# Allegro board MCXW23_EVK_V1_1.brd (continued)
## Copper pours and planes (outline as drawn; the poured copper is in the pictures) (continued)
GND on TOP (solid shape): 52.91,75.6 53,75.64 53.09,75.6 53.2,75.53 53.32,75.5 53.68,75.5 53.78,75.52 53.87,75.57 53.95,75.59 54.02,75.56 54.05,75.53 54.09,75.51 54.15,75.37 54.04,75.28 53.91,75.21 53.86,75.07 53.86,73.97 53.92,73.82 54.07,73.76 54.97,73.76 55.02,73.76 55.06,73.77 55.29,73.75 55.41,73.55 55.41,73.45 55.29,73.25 55.06,73.23 55.02,73.24 54.97,73.24 54.07,73.24 53.92,73.18 53.86,73.03 53.86,72.82 53.14,72.82 53.14,74.05 53.08,74.19 52.94,74.26 52.85,74.3 52.82,74.39 52.82,75.34 52.83,75.36 52.84,75.41 52.84,75.46 52.84,75.54 52.89,75.58
GND on TOP (solid shape): 76.41,99.86 76.41,94.62 76.33,94.5 76.2,94.53 75.99,94.74 75.88,94.81 75.75,94.84 75.46,94.84 75.42,94.89 75.34,94.97 75.34,95.06 75.34,95.12 75.32,95.17 75.32,95.24 75.35,95.3 75.4,95.37 75.42,95.45 75.42,96.05 75.41,96.12 75.37,96.18 75.41,96.24 75.42,96.3 75.42,96.7 75.4,96.76 75.37,96.82 75.41,96.88 75.42,96.95 75.42,97.55 75.41,97.61 75.38,97.67 75.35,97.76 75.39,97.84 75.52,98.03 75.57,98.25 75.4,98.65 75,98.82 74.88,98.81 74.76,98.77 74.58,98.75 74.44,98.86 74.4,98.91 74.36,99 74.4,99.09 74.47,99.2 74.5,99.32 74.5,99.68 74.49,99.75 74.47,99.81 74.49,100.05 74.7,100.16 76.11,100.16
GND on TOP (solid shape): 61.65,77.44 61.87,77.44 61.93,77.34 61.89,77.23 61.84,77.16 61.82,77.07 61.82,75.97 61.88,75.82 62.03,75.76 63.16,75.76 63.16,75.24 62.03,75.24 61.88,75.18 61.82,75.03 61.82,73.89 61.77,73.68 61.57,73.59 60,73.59 59.87,73.56 59.76,73.49 58.75,72.48 57.59,73.64 57.59,76.04 57.87,76.04 58.02,76.1 58.08,76.25 58.08,77.15 58.08,77.2 58.07,77.24 58.05,77.26 58.05,77.42 58.24,77.42 58.25,77.41 59.05,77.41 59.2,77.26 59.31,77.19 59.44,77.16 59.53,77.16 59.6,77.09 59.64,77 59.6,76.91 59.47,76.72 59.43,76.5 60,75.93 60.57,76.5 60.53,76.72 60.4,76.91 60.36,77 60.4,77.09 60.41,77.1 60.5,77.14 60.59,77.1 60.7,77.03 60.82,77 61.18,77 61.39,77.08 61.51,77.27
GND on TOP (solid shape): 70.95,100.91 71.14,100.82 71.19,100.61 71.18,100.56 71.18,100.5 71.24,100.24 71.41,100.04 71.41,99.76 71.44,99.63 71.51,99.52 71.77,99.26 71.88,99.19 72.01,99.16 72.54,99.16 72.58,99.11 72.6,99.09 72.64,99 72.6,98.91 72.53,98.8 72.5,98.68 72.5,98.32 72.54,98.18 72.63,98.06 72.72,97.88 72.65,97.7 72.6,97.63 72.58,97.55 72.58,96.95 72.59,96.88 72.63,96.82 72.59,96.76 72.58,96.7 72.58,96.5 72.47,96.29 72.23,96.27 72.12,96.31 72,96.32 71.88,96.31 71.77,96.27 71.53,96.29 71.42,96.5 71.42,96.7 71.4,96.76 71.37,96.82 71.41,96.88 71.42,96.95 71.42,97.55 71.41,97.61 71.38,97.67 71.35,97.76 71.39,97.84 71.52,98.03 71.57,98.25 71.4,98.65 71,98.82 70.88,98.81 70.76,98.77 70.58,98.75 70.44,98.86 70.4,98.91 70.36,99 70.4,99.09 70.47,99.2 70.5,99.32 70.5,99.68 70.47,99.82 70.38,99.93 70.34,99.97 70.34,100.91
GND on TOP (solid shape): outline of 94 points within 34.41,60.8 40,66.54
GND on TOP (solid shape): outline of 88 points within 77.37,106.31 79.91,112.69
GND on TOP (solid shape): outline of 576 points within 33.98,69.32 45.16,90.76
GND on TOP (solid shape): outline of 215 points within 64.16,64.34 76.41,71.91
GND on TOP (solid shape): outline of 1227 points within 30.59,24.54 44.32,60.73
GND on TOP (solid shape): outline of 1701 points within 47.84,72.17 66.93,91.16
GND on TOP (solid shape): outline of 2078 points within 59.34,68.42 76.91,97.23
GND on TOP (solid shape): outline of 28749 points within 0.5,0.5 104.5,124.5
GND on BOTTOM: 104.5,124.5 104.5,0.5 0.5,0.5 0.5,124.5
GND on IN1: 0.5,0.5 0.5,124.5 104.5,124.5 104.5,0.5
GND on IN2: 104.5,0.5 104.5,124.5 0.5,124.5 0.5,0.5
P5VA on TOP: 13.25,40.75 13.25,42.75 16.25,42.75 16.25,40.75
P5VA on IN2: 13.25,41.5 13.25,42.25 42.75,71.75 44.5,71.75 44.5,66 20,41.5
VBAT_DCDC/VBAT_PMU on TOP: 55.75,22.25 56.75,23.25 61.75,23.25 61.75,18.75 55.75,18.75
VBUS on TOP: 20.25,11.75 20.25,8 31.25,8 31.25,11.75
VBUS on TOP: 16.75,79.75 16.75,74.25 20,74.25 20,79.75
VCC_IF_LINK on IN2: 58.5,95.25 58.5,101 77.75,101 77.75,95.25
(no net) on TOP: 0.5,0.5 0.5,124.5 104.5,124.5 104.5,0.5
MCU_LINK_3V3 on IN2: 39,39.5 61,39.5 61,24.5 53.25,16.75 45.5,16.75 39,23.25
SENSOR_VDD on TOP: 66.5,56.75 63.25,56.75 63.25,54 66.5,54
SYS_5V0 on TOP: 10.75,40.25 10.75,38.25 16.25,38.25 16.25,40.25
SYS_5V0 on TOP: 30.25,112.75 33.25,112.75 33.25,109.25 30.25,109.25
SYS_5V0 on TOP: 12,14.25 12,17 16.75,17 16.75,14.25
SYS_5V0 on TOP: 42.25,113.75 45.25,113.75 45.25,110.25 42.25,110.25
SYS_5V0 on IN2: 54.75,113.75 54.75,103.75 52,103.75 52,109.75 24.73,109.75 24.75,54.25 13,42.5 13,21 16.75,17.25 16.75,16 10.75,16 10.75,45.5 20.75,55.5 20.75,113.75
USB_1V5 on TOP: 25.75,110.75 29.5,110.75 29.5,105.75 25.75,105.75
VIO on TOP: 18.5,120.5 14,120.5 13.5,121 12,121 12,118 18.5,118
VIO on IN2: 16.25,120 4,107.75 4,55.5 83.5,55.5 83.5,60.5 84.5,61.5 84.5,77.75 83.25,79 83.25,93.25 87,97 87,120
N12422390 on BOTTOM: 8,87.5 13,87.5 23.5,98 44,98 44.5,98.5 44.5,104 44,104.5 22,104.5 8,90.5
N12480389 on TOP: 10.5,7.75 10.5,5.25 13,5.25 13,3.5 14,3.5 14,5.25 14.75,5.25 14.75,7.75
N12480952 on TOP: 14.75,8 14.75,10.75 10.5,10.75 10.5,8
N12627699 on TOP: 15.25,13.75 15.25,8 19.75,8 19.75,13.75

Small or netless copper shapes (teardrops, artwork), in the pictures only: 8 on TOP

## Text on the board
TOP: Y.DIEUMEGARD | 16/05/22 | V1.1
Ref Des/Silkscreen Top: SPI/I2C | VCOM | SWD | USB | BAT | GND | 1V5 | 3V | SNS3 | SNS1 | VBAT | VOLTAGE SELECT | V1.1 | SNS4 | SNS2 | MCXW23-EVK-BB | NFC | IO VOLTAGE | I2C PU | FLEXCOMM 1 | FLEXCOMM 0 | FLEXCOMM 2 | USB_PWR | MCU Link | S/N | SENSOR | SELECT | PWR | NC | 3V3 | MOSI | SDA | MISO | SCL | USER | SCK | TX | CS | RX | RST | INT | NFC_3V0/PWM | PIO0_8/INT | ISP | WAKEUP | RESET
User.29: FIGURE | SIZE | 0.3 | 0.5 | 0.6 | 1.0 | 3.2 | 1.5 | 0.75x0.65 | 1.3x0.8 | DRILL CHART: TOP to BOTTOM | ALL UNITS ARE IN MILLIMETERS | TOLERANCE | +0.0/-0.0 | +0.05/-0.05 | PLATED | NON-PLATED | QTY | 577 | 136 | 20 | 180 | 4
